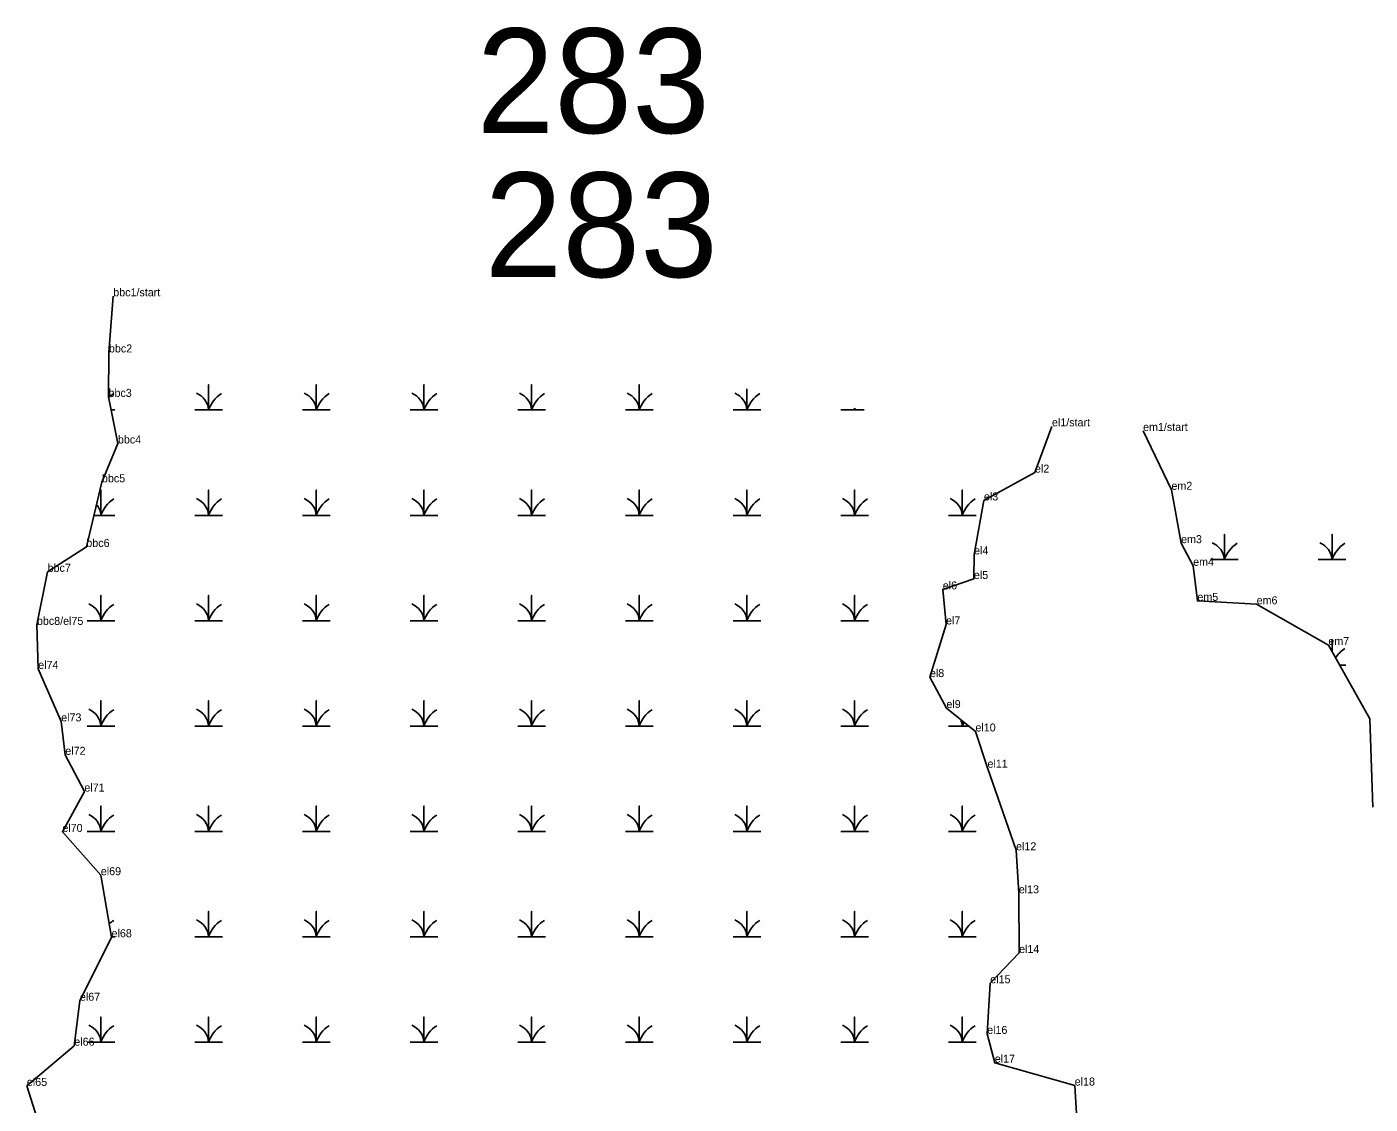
# Model space of a CAD drawing. Extents: x 2072529 to 2268796, y 436423 to 470406.
# Drawn here: x 2244102 to 2244941, y 440851 to 441524 of the extents above; entities that cross this region are included whole.
import ezdxf

# ---------------------------------------------------------------- set-up
doc = ezdxf.new("R2010")
doc.units = 0
for name, color, linetype in [('Default', 7, 'Continuous'), ('Exist Environmental Wetland Boundary', 7, 'Continuous'), ('Exist Environmental Wetland Boundary Cogo Comment', 7, 'Continuous'), ('Exist Hydro Swamp or Marsh', 7, 'Continuous'), ('Old_Level_20', 7, 'Continuous')]:
    doc.layers.add(name, color=color, linetype=linetype)

msp = doc.modelspace()

# ---------------------------------------------------------------- linework, layer by layer
at = {"layer": 'Exist Environmental Wetland Boundary'}
for points in [[(2244155.54, 441355.9), (2244152.85, 441320.84), (2244152.59, 441293.07), (2244158.46, 441263.97), (2244148.49, 441239.74), (2244138.74, 441199.35), (2244114.55, 441183.81), (2244107.87, 441150.67), (2244108.69, 441123.2), (2244123.02, 441090.4), (2244125.6, 441069.52), (2244137.5, 441046.59), (2244123.75, 441021.35), (2244147.8, 440994.34), (2244154.49, 440955.58), (2244134.72, 440915.93), (2244131.23, 440887.85), (2244101.59, 440862.71), (2244118.03, 440810.75)], [(2244758.12, 440827.95), (2244756.06, 440862.97), (2244706.15, 440877.24), (2244701.38, 440895.2), (2244703.3, 440926.86), (2244721.34, 440945.75), (2244721.14, 440983.03), (2244719.43, 441009.88), (2244701.59, 441061.49), (2244694.06, 441084.1), (2244675.93, 441098.73), (2244665.63, 441118.08), (2244675.71, 441150.96), (2244673.66, 441172.82), (2244693.09, 441179.35), (2244693.2, 441194.68), (2244699.37, 441228.4), (2244731.25, 441245.79), (2244741.86, 441274.68)], [(2244798.77, 441271.79), (2244816.47, 441235.05), (2244822.51, 441201.72), (2244830.04, 441187.58), (2244832.7, 441165.66), (2244869.7, 441163.55), (2244914.49, 441138.07), (2244940.44, 441091.96), (2244942.17, 441036.87)]]:
    msp.add_lwpolyline(points, dxfattribs=at)
at = {"layer": 'Exist Hydro Swamp or Marsh'}
for points in [[(2244206.49, 441284.89), (2244215.09, 441284.89), (2244215.09, 441300.68), (2244215.09, 441284.89), (2244223.69, 441284.89)], [(2244273.74, 441284.89), (2244282.34, 441284.89), (2244282.34, 441300.68), (2244282.34, 441284.89), (2244290.94, 441284.89)], [(2244340.99, 441284.89), (2244349.59, 441284.89), (2244349.59, 441300.68), (2244349.59, 441284.89), (2244358.19, 441284.89)], [(2244408.24, 441284.89), (2244416.84, 441284.89), (2244416.84, 441300.68), (2244416.84, 441284.89), (2244425.44, 441284.89)], [(2244475.49, 441284.89), (2244484.09, 441284.89), (2244484.09, 441300.68), (2244484.09, 441284.89), (2244492.69, 441284.89)], [(2244542.74, 441284.89), (2244551.34, 441284.89), (2244551.34, 441298.06)], [(2244551.34, 441298.06), (2244551.34, 441284.89), (2244559.94, 441284.89)], [(2244609.99, 441284.89), (2244618.59, 441284.89), (2244618.59, 441286.01)], [(2244618.59, 441286.01), (2244618.59, 441284.89), (2244624.52, 441284.89)], [(2244154.24, 441284.89), (2244156.44, 441284.89)], [(2244143.5, 441219.09), (2244147.84, 441219.09), (2244147.84, 441234.88), (2244147.84, 441219.09), (2244156.44, 441219.09)], [(2244206.49, 441219.09), (2244215.09, 441219.09), (2244215.09, 441234.88), (2244215.09, 441219.09), (2244223.69, 441219.09)], [(2244273.74, 441219.09), (2244282.34, 441219.09), (2244282.34, 441234.88), (2244282.34, 441219.09), (2244290.94, 441219.09)], [(2244340.99, 441219.09), (2244349.59, 441219.09), (2244349.59, 441234.88), (2244349.59, 441219.09), (2244358.19, 441219.09)], [(2244408.24, 441219.09), (2244416.84, 441219.09), (2244416.84, 441234.88), (2244416.84, 441219.09), (2244425.44, 441219.09)], [(2244475.49, 441219.09), (2244484.09, 441219.09), (2244484.09, 441234.88), (2244484.09, 441219.09), (2244492.69, 441219.09)], [(2244542.74, 441219.09), (2244551.34, 441219.09), (2244551.34, 441234.88), (2244551.34, 441219.09), (2244559.94, 441219.09)], [(2244609.99, 441219.09), (2244618.59, 441219.09), (2244618.59, 441234.88), (2244618.59, 441219.09), (2244627.19, 441219.09)], [(2244677.24, 441219.09), (2244685.84, 441219.09), (2244685.84, 441234.88), (2244685.84, 441219.09), (2244694.44, 441219.09)], [(2244840.93, 441191.42), (2244849.53, 441191.42), (2244849.53, 441207.2), (2244849.53, 441191.42), (2244858.13, 441191.42)], [(2244908.18, 441191.42), (2244916.78, 441191.42), (2244916.78, 441207.2), (2244916.78, 441191.42), (2244925.38, 441191.42)], [(2244139.24, 441153.29), (2244147.84, 441153.29), (2244147.84, 441169.08), (2244147.84, 441153.29), (2244156.44, 441153.29)], [(2244206.49, 441153.29), (2244215.09, 441153.29), (2244215.09, 441169.08), (2244215.09, 441153.29), (2244223.69, 441153.29)], [(2244273.74, 441153.29), (2244282.34, 441153.29), (2244282.34, 441169.08), (2244282.34, 441153.29), (2244290.94, 441153.29)], [(2244340.99, 441153.29), (2244349.59, 441153.29), (2244349.59, 441169.08), (2244349.59, 441153.29), (2244358.19, 441153.29)], [(2244408.24, 441153.29), (2244416.84, 441153.29), (2244416.84, 441169.08), (2244416.84, 441153.29), (2244425.44, 441153.29)], [(2244475.49, 441153.29), (2244484.09, 441153.29), (2244484.09, 441169.08), (2244484.09, 441153.29), (2244492.69, 441153.29)], [(2244542.74, 441153.29), (2244551.34, 441153.29), (2244551.34, 441169.08), (2244551.34, 441153.29), (2244559.94, 441153.29)], [(2244609.99, 441153.29), (2244618.59, 441153.29), (2244618.59, 441169.08), (2244618.59, 441153.29), (2244627.19, 441153.29)], [(2244916.78, 441134), (2244916.78, 441141.4), (2244916.78, 441134)], [(2244921.5, 441125.62), (2244925.38, 441125.62)], [(2244139.24, 441087.49), (2244147.84, 441087.49), (2244147.84, 441103.28), (2244147.84, 441087.49), (2244156.44, 441087.49)], [(2244206.49, 441087.49), (2244215.09, 441087.49), (2244215.09, 441103.28), (2244215.09, 441087.49), (2244223.69, 441087.49)], [(2244273.74, 441087.49), (2244282.34, 441087.49), (2244282.34, 441103.28), (2244282.34, 441087.49), (2244290.94, 441087.49)], [(2244340.99, 441087.49), (2244349.59, 441087.49), (2244349.59, 441103.28), (2244349.59, 441087.49), (2244358.19, 441087.49)], [(2244408.24, 441087.49), (2244416.84, 441087.49), (2244416.84, 441103.28), (2244416.84, 441087.49), (2244425.44, 441087.49)], [(2244475.49, 441087.49), (2244484.09, 441087.49), (2244484.09, 441103.28), (2244484.09, 441087.49), (2244492.69, 441087.49)], [(2244542.74, 441087.49), (2244551.34, 441087.49), (2244551.34, 441103.28), (2244551.34, 441087.49), (2244559.94, 441087.49)], [(2244609.99, 441087.49), (2244618.59, 441087.49), (2244618.59, 441103.28), (2244618.59, 441087.49), (2244627.19, 441087.49)], [(2244677.24, 441087.49), (2244685.84, 441087.49), (2244685.84, 441090.73)], [(2244685.84, 441090.73), (2244685.84, 441087.49), (2244689.85, 441087.49)], [(2244139.24, 441021.69), (2244147.84, 441021.69), (2244147.84, 441037.48), (2244147.84, 441021.69), (2244156.44, 441021.69)], [(2244206.49, 441021.69), (2244215.09, 441021.69), (2244215.09, 441037.48), (2244215.09, 441021.69), (2244223.69, 441021.69)], [(2244273.74, 441021.69), (2244282.34, 441021.69), (2244282.34, 441037.48), (2244282.34, 441021.69), (2244290.94, 441021.69)], [(2244340.99, 441021.69), (2244349.59, 441021.69), (2244349.59, 441037.48), (2244349.59, 441021.69), (2244358.19, 441021.69)], [(2244408.24, 441021.69), (2244416.84, 441021.69), (2244416.84, 441037.48), (2244416.84, 441021.69), (2244425.44, 441021.69)], [(2244475.49, 441021.69), (2244484.09, 441021.69), (2244484.09, 441037.48), (2244484.09, 441021.69), (2244492.69, 441021.69)], [(2244542.74, 441021.69), (2244551.34, 441021.69), (2244551.34, 441037.48), (2244551.34, 441021.69), (2244559.94, 441021.69)], [(2244609.99, 441021.69), (2244618.59, 441021.69), (2244618.59, 441037.48), (2244618.59, 441021.69), (2244627.19, 441021.69)], [(2244677.24, 441021.69), (2244685.84, 441021.69), (2244685.84, 441037.48), (2244685.84, 441021.69), (2244694.44, 441021.69)], [(2244206.49, 440955.89), (2244215.09, 440955.89), (2244215.09, 440971.68), (2244215.09, 440955.89), (2244223.69, 440955.89)], [(2244273.74, 440955.89), (2244282.34, 440955.89), (2244282.34, 440971.68), (2244282.34, 440955.89), (2244290.94, 440955.89)], [(2244340.99, 440955.89), (2244349.59, 440955.89), (2244349.59, 440971.68), (2244349.59, 440955.89), (2244358.19, 440955.89)], [(2244408.24, 440955.89), (2244416.84, 440955.89), (2244416.84, 440971.68), (2244416.84, 440955.89), (2244425.44, 440955.89)], [(2244475.49, 440955.89), (2244484.09, 440955.89), (2244484.09, 440971.68), (2244484.09, 440955.89), (2244492.69, 440955.89)], [(2244542.74, 440955.89), (2244551.34, 440955.89), (2244551.34, 440971.68), (2244551.34, 440955.89), (2244559.94, 440955.89)], [(2244609.99, 440955.89), (2244618.59, 440955.89), (2244618.59, 440971.68), (2244618.59, 440955.89), (2244627.19, 440955.89)], [(2244677.24, 440955.89), (2244685.84, 440955.89), (2244685.84, 440971.68), (2244685.84, 440955.89), (2244694.44, 440955.89)], [(2244154.44, 440955.89), (2244156.44, 440955.89)], [(2244139.24, 440890.09), (2244147.84, 440890.09), (2244147.84, 440905.88), (2244147.84, 440890.09), (2244156.44, 440890.09)], [(2244206.49, 440890.09), (2244215.09, 440890.09), (2244215.09, 440905.88), (2244215.09, 440890.09), (2244223.69, 440890.09)], [(2244273.74, 440890.09), (2244282.34, 440890.09), (2244282.34, 440905.88), (2244282.34, 440890.09), (2244290.94, 440890.09)], [(2244340.99, 440890.09), (2244349.59, 440890.09), (2244349.59, 440905.88), (2244349.59, 440890.09), (2244358.19, 440890.09)], [(2244408.24, 440890.09), (2244416.84, 440890.09), (2244416.84, 440905.88), (2244416.84, 440890.09), (2244425.44, 440890.09)], [(2244475.49, 440890.09), (2244484.09, 440890.09), (2244484.09, 440905.88), (2244484.09, 440890.09), (2244492.69, 440890.09)], [(2244542.74, 440890.09), (2244551.34, 440890.09), (2244551.34, 440905.88), (2244551.34, 440890.09), (2244559.94, 440890.09)], [(2244609.99, 440890.09), (2244618.59, 440890.09), (2244618.59, 440905.88), (2244618.59, 440890.09), (2244627.19, 440890.09)], [(2244677.24, 440890.09), (2244685.84, 440890.09), (2244685.84, 440905.88), (2244685.84, 440890.09), (2244694.44, 440890.09)]]:
    msp.add_lwpolyline(points, dxfattribs=at)
for centre, radius, start, end in [((2244166.08, 441278.83), 19.22, 122.12745, 134.18504), ((2244202.82, 441284.01), 12.3, 4.14034, 67.53497), ((2244233.33, 441278.83), 19.22, 122.12745, 161.62219), ((2244270.07, 441284.01), 12.3, 4.14034, 67.53497), ((2244300.58, 441278.83), 19.22, 122.12745, 161.62219), ((2244337.32, 441284.01), 12.3, 4.14034, 67.53497), ((2244367.83, 441278.83), 19.22, 122.12745, 161.62219), ((2244404.57, 441284.01), 12.3, 4.14034, 67.53497), ((2244435.08, 441278.83), 19.22, 122.12745, 161.62219), ((2244471.82, 441284.01), 12.3, 4.14034, 67.53497), ((2244502.33, 441278.83), 19.22, 122.12745, 161.62219), ((2244539.07, 441284.01), 12.3, 4.14034, 67.53497), ((2244569.58, 441278.83), 19.22, 122.12745, 161.62219), ((2244606.32, 441284.01), 12.3, 4.14034, 9.4845), ((2244636.83, 441278.83), 19.22, 158.30759, 161.62219), ((2244166.08, 441213.03), 19.22, 122.12745, 161.62219), ((2244202.82, 441218.21), 12.3, 4.14034, 67.53497), ((2244233.33, 441213.03), 19.22, 122.12745, 161.62219), ((2244270.07, 441218.21), 12.3, 4.14034, 67.53497), ((2244300.58, 441213.03), 19.22, 122.12745, 161.62219), ((2244337.32, 441218.21), 12.3, 4.14034, 67.53497), ((2244367.83, 441213.03), 19.22, 122.12745, 161.62219), ((2244404.57, 441218.21), 12.3, 4.14034, 67.53497), ((2244435.08, 441213.03), 19.22, 122.12745, 161.62219), ((2244471.82, 441218.21), 12.3, 4.14034, 67.53497), ((2244502.33, 441213.03), 19.22, 122.12745, 161.62219), ((2244539.07, 441218.21), 12.3, 4.14034, 67.53497), ((2244569.58, 441213.03), 19.22, 122.12745, 161.62219), ((2244606.32, 441218.21), 12.3, 4.14034, 67.53497), ((2244636.83, 441213.03), 19.22, 122.12745, 161.62219), ((2244673.57, 441218.21), 12.3, 4.14034, 67.53497), ((2244704.08, 441213.03), 19.22, 122.12745, 161.62219), ((2244135.57, 441218.21), 12.3, 4.14034, 38.8533), ((2244837.27, 441190.53), 12.3, 4.14034, 67.53497), ((2244867.77, 441185.36), 19.22, 122.12745, 161.62219), ((2244904.52, 441190.53), 12.3, 4.14034, 67.53497), ((2244935.02, 441185.36), 19.22, 122.12745, 161.62219), ((2244135.57, 441152.41), 12.3, 4.14034, 67.53497), ((2244166.08, 441147.23), 19.22, 122.12745, 161.62219), ((2244202.82, 441152.41), 12.3, 4.14034, 67.53497), ((2244233.33, 441147.23), 19.22, 122.12745, 161.62219), ((2244270.07, 441152.41), 12.3, 4.14034, 67.53497), ((2244300.58, 441147.23), 19.22, 122.12745, 161.62219), ((2244337.32, 441152.41), 12.3, 4.14034, 67.53497), ((2244367.83, 441147.23), 19.22, 122.12745, 161.62219), ((2244404.57, 441152.41), 12.3, 4.14034, 67.53497), ((2244435.08, 441147.23), 19.22, 122.12745, 161.62219), ((2244471.82, 441152.41), 12.3, 4.14034, 67.53497), ((2244502.33, 441147.23), 19.22, 122.12745, 161.62219), ((2244539.07, 441152.41), 12.3, 4.14034, 67.53497), ((2244569.58, 441147.23), 19.22, 122.12745, 161.62219), ((2244606.32, 441152.41), 12.3, 4.14034, 67.53497), ((2244636.83, 441147.23), 19.22, 122.12745, 161.62219), ((2244935.02, 441119.56), 19.22, 122.12745, 146.66499), ((2244135.57, 441086.61), 12.3, 4.14034, 67.53497), ((2244166.08, 441081.43), 19.22, 122.12745, 161.62219), ((2244202.82, 441086.61), 12.3, 4.14034, 67.53497), ((2244233.33, 441081.43), 19.22, 122.12745, 161.62219), ((2244270.07, 441086.61), 12.3, 4.14034, 67.53497), ((2244300.58, 441081.43), 19.22, 122.12745, 161.62219), ((2244337.32, 441086.61), 12.3, 4.14034, 67.53497), ((2244367.83, 441081.43), 19.22, 122.12745, 161.62219), ((2244404.57, 441086.61), 12.3, 4.14034, 67.53497), ((2244435.08, 441081.43), 19.22, 122.12745, 161.62219), ((2244471.82, 441086.61), 12.3, 4.14034, 67.53497), ((2244502.33, 441081.43), 19.22, 122.12745, 161.62219), ((2244539.07, 441086.61), 12.3, 4.14034, 67.53497), ((2244569.58, 441081.43), 19.22, 122.12745, 161.62219), ((2244606.32, 441086.61), 12.3, 4.14034, 67.53497), ((2244636.83, 441081.43), 19.22, 122.12745, 161.62219), ((2244673.57, 441086.61), 12.3, 4.14034, 23.63267), ((2244704.08, 441081.43), 19.22, 153.78651, 161.62219), ((2244135.57, 441020.81), 12.3, 4.14034, 67.53497), ((2244166.08, 441015.63), 19.22, 122.12745, 161.62219), ((2244202.82, 441020.81), 12.3, 4.14034, 67.53497), ((2244233.33, 441015.63), 19.22, 122.12745, 161.62219), ((2244270.07, 441020.81), 12.3, 4.14034, 67.53497), ((2244300.58, 441015.63), 19.22, 122.12745, 161.62219), ((2244337.32, 441020.81), 12.3, 4.14034, 67.53497), ((2244367.83, 441015.63), 19.22, 122.12745, 161.62219), ((2244404.57, 441020.81), 12.3, 4.14034, 67.53497), ((2244435.08, 441015.63), 19.22, 122.12745, 161.62219), ((2244471.82, 441020.81), 12.3, 4.14034, 67.53497), ((2244502.33, 441015.63), 19.22, 122.12745, 161.62219), ((2244539.07, 441020.81), 12.3, 4.14034, 67.53497), ((2244569.58, 441015.63), 19.22, 122.12745, 161.62219), ((2244606.32, 441020.81), 12.3, 4.14034, 67.53497), ((2244636.83, 441015.63), 19.22, 122.12745, 161.62219), ((2244673.57, 441020.81), 12.3, 4.14034, 67.53497), ((2244704.08, 441015.63), 19.22, 122.12745, 161.62219), ((2244202.82, 440955.01), 12.3, 4.14034, 67.53497), ((2244270.07, 440955.01), 12.3, 4.14034, 67.53497), ((2244337.32, 440955.01), 12.3, 4.14034, 67.53497), ((2244404.57, 440955.01), 12.3, 4.14034, 67.53497), ((2244471.82, 440955.01), 12.3, 4.14034, 67.53497), ((2244539.07, 440955.01), 12.3, 4.14034, 67.53497), ((2244606.32, 440955.01), 12.3, 4.14034, 67.53497), ((2244673.57, 440955.01), 12.3, 4.14034, 67.53497), ((2244166.08, 440949.83), 19.22, 122.12745, 132.69891), ((2244233.33, 440949.83), 19.22, 122.12745, 161.62219), ((2244300.58, 440949.83), 19.22, 122.12745, 161.62219), ((2244367.83, 440949.83), 19.22, 122.12745, 161.62219), ((2244435.08, 440949.83), 19.22, 122.12745, 161.62219), ((2244502.33, 440949.83), 19.22, 122.12745, 161.62219), ((2244569.58, 440949.83), 19.22, 122.12745, 161.62219), ((2244636.83, 440949.83), 19.22, 122.12745, 161.62219), ((2244704.08, 440949.83), 19.22, 122.12745, 161.62219), ((2244135.57, 440889.21), 12.3, 4.14034, 67.53497), ((2244166.08, 440884.03), 19.22, 122.12745, 161.62219), ((2244202.82, 440889.21), 12.3, 4.14034, 67.53497), ((2244233.33, 440884.03), 19.22, 122.12745, 161.62219), ((2244270.07, 440889.21), 12.3, 4.14034, 67.53497), ((2244300.58, 440884.03), 19.22, 122.12745, 161.62219), ((2244337.32, 440889.21), 12.3, 4.14034, 67.53497), ((2244367.83, 440884.03), 19.22, 122.12745, 161.62219), ((2244404.57, 440889.21), 12.3, 4.14034, 67.53497), ((2244435.08, 440884.03), 19.22, 122.12745, 161.62219), ((2244471.82, 440889.21), 12.3, 4.14034, 67.53497), ((2244502.33, 440884.03), 19.22, 122.12745, 161.62219), ((2244539.07, 440889.21), 12.3, 4.14034, 67.53497), ((2244569.58, 440884.03), 19.22, 122.12745, 161.62219), ((2244606.32, 440889.21), 12.3, 4.14034, 67.53497), ((2244636.83, 440884.03), 19.22, 122.12745, 161.62219), ((2244673.57, 440889.21), 12.3, 4.14034, 67.53497), ((2244704.08, 440884.03), 19.22, 122.12745, 161.62219)]:
    msp.add_arc(centre, radius, start, end, dxfattribs=at)
at = {"layer": 'Old_Level_20'}
for p, q in [((2244155.54, 441355.9), (2244155.54, 441355.9)), ((2244152.85, 441320.84), (2244152.85, 441320.84)), ((2244152.59, 441293.07), (2244152.59, 441293.07)), ((2244741.86, 441274.68), (2244741.86, 441274.68)), ((2244798.77, 441271.79), (2244798.77, 441271.79)), ((2244158.46, 441263.97), (2244158.46, 441263.97)), ((2244731.25, 441245.79), (2244731.25, 441245.79)), ((2244148.49, 441239.74), (2244148.49, 441239.74)), ((2244816.47, 441235.05), (2244816.47, 441235.05)), ((2244699.37, 441228.4), (2244699.37, 441228.4)), ((2244822.51, 441201.72), (2244822.51, 441201.72)), ((2244138.74, 441199.35), (2244138.74, 441199.35)), ((2244693.2, 441194.68), (2244693.2, 441194.68)), ((2244830.04, 441187.58), (2244830.04, 441187.58)), ((2244114.55, 441183.81), (2244114.55, 441183.81)), ((2244693.09, 441179.35), (2244693.09, 441179.35)), ((2244673.66, 441172.82), (2244673.66, 441172.82)), ((2244832.7, 441165.66), (2244832.7, 441165.66)), ((2244869.7, 441163.55), (2244869.7, 441163.55)), ((2244675.71, 441150.96), (2244675.71, 441150.96)), ((2244107.87, 441150.67), (2244107.87, 441150.67)), ((2244914.49, 441138.07), (2244914.49, 441138.07)), ((2244108.69, 441123.2), (2244108.69, 441123.2)), ((2244665.63, 441118.08), (2244665.63, 441118.08)), ((2244675.93, 441098.73), (2244675.93, 441098.73)), ((2244123.02, 441090.4), (2244123.02, 441090.4)), ((2244694.06, 441084.1), (2244694.06, 441084.1)), ((2244940.44, 441091.96), (2244940.44, 441091.96)), ((2244125.6, 441069.52), (2244125.6, 441069.52)), ((2244701.59, 441061.49), (2244701.59, 441061.49)), ((2244137.5, 441046.59), (2244137.5, 441046.59)), ((2244123.75, 441021.35), (2244123.75, 441021.35)), ((2244719.43, 441009.88), (2244719.43, 441009.88)), ((2244147.8, 440994.34), (2244147.8, 440994.34)), ((2244721.14, 440983.03), (2244721.14, 440983.03)), ((2244154.49, 440955.58), (2244154.49, 440955.58)), ((2244721.34, 440945.75), (2244721.34, 440945.75)), ((2244703.3, 440926.86), (2244703.3, 440926.86)), ((2244134.72, 440915.93), (2244134.72, 440915.93)), ((2244701.38, 440895.2), (2244701.38, 440895.2)), ((2244131.23, 440887.85), (2244131.23, 440887.85)), ((2244706.15, 440877.24), (2244706.15, 440877.24)), ((2244101.59, 440862.71), (2244101.59, 440862.71)), ((2244756.06, 440862.97), (2244756.06, 440862.97))]:
    msp.add_line(p, q, dxfattribs=at)

# ---------------------------------------------------------------- texts
at = {"layer": 'Default'}
for p in [(2244382.45, 441457.86), (2244387.44, 441367.9)]:
    msp.add_text('283', height=65.34, dxfattribs=at).set_placement(p)
at = {"layer": 'Exist Environmental Wetland Boundary Cogo Comment'}
for s, p in [('bbc1/start', (2244155.54, 441355.9)), ('bbc2', (2244152.85, 441320.84)), ('bbc3', (2244152.59, 441293.07)), ('el1/start', (2244741.86, 441274.68)), ('em1/start', (2244798.77, 441271.79)), ('bbc4', (2244158.46, 441263.97)), ('bbc5', (2244148.49, 441239.74)), ('el2', (2244731.25, 441245.79)), ('em2', (2244816.47, 441235.05)), ('el3', (2244699.37, 441228.4)), ('bbc6', (2244138.74, 441199.35)), ('em3', (2244822.51, 441201.72)), ('el4', (2244693.2, 441194.68)), ('bbc7', (2244114.55, 441183.81)), ('el5', (2244693.09, 441179.35)), ('em4', (2244830.04, 441187.58)), ('el6', (2244673.66, 441172.82)), ('em5', (2244832.7, 441165.66)), ('em6', (2244869.7, 441163.55)), ('bbc8/el75', (2244107.87, 441150.67)), ('el7', (2244675.71, 441150.96)), ('em7', (2244914.49, 441138.07)), ('el74', (2244108.69, 441123.2)), ('el8', (2244665.63, 441118.08)), ('el9', (2244675.93, 441098.73)), ('el73', (2244123.02, 441090.4)), ('el10', (2244694.06, 441084.1)), ('el72', (2244125.6, 441069.52)), ('el11', (2244701.59, 441061.49)), ('el71', (2244137.5, 441046.59)), ('el70', (2244123.75, 441021.35)), ('el12', (2244719.43, 441009.88)), ('el69', (2244147.8, 440994.34)), ('el13', (2244721.14, 440983.03)), ('el68', (2244154.49, 440955.58)), ('el14', (2244721.34, 440945.75)), ('el15', (2244703.3, 440926.86)), ('el67', (2244134.72, 440915.93)), ('el16', (2244701.38, 440895.2)), ('el66', (2244131.23, 440887.85)), ('el17', (2244706.15, 440877.24)), ('el65', (2244101.59, 440862.71)), ('el18', (2244756.06, 440862.97))]:
    msp.add_text(s, height=5, dxfattribs=at).set_placement(p)

doc.saveas('drawing.dxf')
